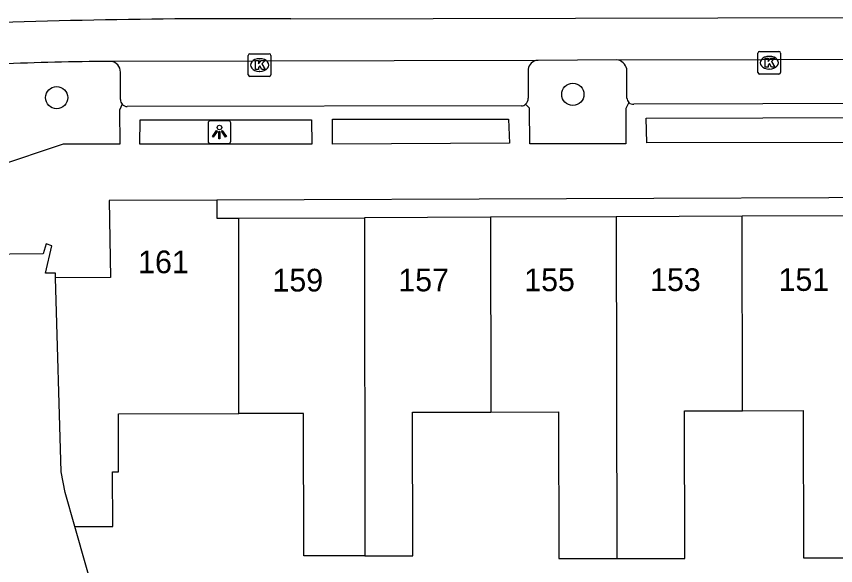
# Model space of a CAD drawing. Extents: x 159718 to 160783, y 383290 to 384030.
# Drawn here: x 160075.74 to 160111.85, y 383730.22 to 383754.43 of the extents above; entities that cross this region are included whole.
import ezdxf

# ---------------------------------------------------------------- set-up
doc = ezdxf.new("R2010")
doc.units = 0
for name, color, linetype in [('IMGEO_Boom', 7, 'Continuous'), ('IMGEO_Kolk', 7, 'Continuous'), ('IMGEO_Lichtpunt', 7, 'Continuous'), ('IMGEO_Pand', 7, 'Continuous'), ('IMGEO_Pand_nummerreeks', 7, 'Continuous'), ('IMGEO_Parkeervlak_open', 7, 'Continuous'), ('IMGEO_Rijbaan_lokaal_gesloten', 7, 'Continuous'), ('IMGEO_Voetpad_open', 7, 'Continuous')]:
    doc.layers.add(name, color=color, linetype=linetype)

msp = doc.modelspace()

# ---------------------------------------------------------------- linework, layer by layer
at = {"layer": 'IMGEO_Boom'}
for centre in [(160077.515, 383750.855), (160100.268, 383750.997)]:
    msp.add_circle(centre, 0.489, dxfattribs=at)
at = {"layer": 'IMGEO_Kolk'}
for p, q in [((160086.037, 383752.789), (160086.889, 383752.789)), ((160108.428, 383751.964), (160108.428, 383752.816)), ((160108.503, 383752.89), (160109.355, 383752.89)), ((160109.429, 383752.816), (160109.429, 383751.964)), ((160085.962, 383751.863), (160085.962, 383752.715)), ((160086.45, 383752.569), (160086.475, 383752.569)), ((160086.963, 383752.715), (160086.963, 383751.863)), ((160108.916, 383752.67), (160108.941, 383752.67)), ((160108.939, 383752.11), (160108.914, 383752.11)), ((160086.889, 383751.789), (160086.037, 383751.789)), ((160086.473, 383752.009), (160086.448, 383752.009)), ((160109.355, 383751.89), (160108.503, 383751.89))]:
    msp.add_line(p, q, dxfattribs=at)
for points in [[(160086.037, 383752.789), (160086.889, 383752.789)], [(160108.428, 383751.964), (160108.428, 383752.816)], [(160108.503, 383752.89), (160109.355, 383752.89)], [(160109.429, 383752.816), (160109.429, 383751.964)], [(160085.962, 383751.863), (160085.962, 383752.715)], [(160086.283, 383752.489), (160086.406, 383752.489), (160086.406, 383752.338), (160086.536, 383752.489), (160086.7, 383752.489), (160086.554, 383752.338), (160086.707, 383752.089), (160086.555, 383752.089), (160086.47, 383752.253), (160086.406, 383752.186), (160086.406, 383752.089), (160086.283, 383752.089), (160086.283, 383752.489)], [(160086.963, 383752.715), (160086.963, 383751.863)], [(160108.749, 383752.59), (160108.872, 383752.59), (160108.872, 383752.439), (160109.002, 383752.59), (160109.166, 383752.59), (160109.02, 383752.439), (160109.173, 383752.19), (160109.021, 383752.19), (160108.936, 383752.354), (160108.872, 383752.287), (160108.872, 383752.19), (160108.749, 383752.19), (160108.749, 383752.59)], [(160086.889, 383751.789), (160086.037, 383751.789)], [(160109.355, 383751.89), (160108.503, 383751.89)]]:
    msp.add_lwpolyline(points, dxfattribs=at)
for centre, start, end in [((160086.039, 383752.713), 91.552, 178.448), ((160086.039, 383752.713), 91.552, 178.448), ((160086.887, 383752.713), 1.552, 88.448), ((160086.887, 383752.713), 1.552, 88.448), ((160108.505, 383752.814), 91.552, 178.448), ((160108.505, 383752.814), 91.552, 178.448), ((160109.353, 383752.814), 1.552, 88.448), ((160109.353, 383752.814), 1.552, 88.448), ((160086.039, 383751.865), 181.552, 268.448), ((160086.039, 383751.865), 181.552, 268.448), ((160086.887, 383751.865), 271.552, 358.448), ((160086.887, 383751.865), 271.552, 358.448), ((160108.505, 383751.966), 181.552, 268.448), ((160108.505, 383751.966), 181.552, 268.448), ((160109.353, 383751.966), 271.552, 358.448), ((160109.353, 383751.966), 271.552, 358.448)]:
    msp.add_arc(centre, 0.0765, start, end, dxfattribs=at)
for centre, major_axis, ratio, start_param, end_param in [((160086.449, 383752.289), (-0.387, 0.002), 0.722429, 4.712389, 7.853982), ((160086.474, 383752.289), (-0.39, 0.002), 0.717154, 1.570796, 4.712389), ((160108.915, 383752.39), (-0.387, 0.002), 0.722429, 4.712389, 7.853982), ((160108.94, 383752.39), (-0.39, 0.002), 0.717154, 1.570796, 4.712389)]:
    msp.add_ellipse(centre, major_axis=major_axis, ratio=ratio, start_param=start_param, end_param=end_param, dxfattribs=at)
at = {"layer": 'IMGEO_Lichtpunt'}
for p, q in [((160084.192, 383749.737), (160084.192, 383748.93)), ((160084.192, 383749.737), (160084.192, 383748.93)), ((160085.094, 383749.832), (160084.286, 383749.832)), ((160085.094, 383749.832), (160084.286, 383749.832)), ((160085.188, 383748.93), (160085.188, 383749.737)), ((160085.188, 383748.93), (160085.188, 383749.737)), ((160084.286, 383748.836), (160085.094, 383748.836)), ((160084.286, 383748.836), (160085.094, 383748.836))]:
    msp.add_line(p, q, dxfattribs=at)
for points in [[(160084.566, 383749.401), (160084.605, 383749.373), (160084.417, 383749.111), (160084.379, 383749.138), (160084.566, 383749.401)], [(160084.668, 383749.353), (160084.715, 383749.353), (160084.715, 383749.031), (160084.668, 383749.031), (160084.668, 383749.353)], [(160084.778, 383749.373), (160084.816, 383749.4), (160085.003, 383749.138), (160084.964, 383749.11), (160084.778, 383749.373)]]:
    msp.add_lwpolyline(points, dxfattribs=at)
msp.add_circle((160084.691, 383749.535), 0.0994, dxfattribs=at)
for centre, start, end in [((160084.286, 383749.737), 90, 180), ((160084.286, 383749.737), 90, 180), ((160085.094, 383749.737), 0, 90), ((160085.094, 383749.737), 0, 90), ((160084.286, 383748.93), 180, 270), ((160084.286, 383748.93), 180, 270), ((160085.094, 383748.93), 270, 0), ((160085.094, 383748.93), 270, 360)]:
    msp.add_arc(centre, 0.0946, start, end, dxfattribs=at)
at = {"layer": 'IMGEO_Pand'}
for points in [[(160084.576, 383746.335), (160079.829, 383746.321), (160079.887, 383742.919), (160077.468, 383742.909)], [(160084.576, 383746.335), (160084.578, 383745.535), (160085.54, 383745.538)], [(160096.637, 383745.58), (160091.088, 383745.559)], [(160102.185, 383745.601), (160096.637, 383745.58)], [(160096.637, 383745.58), (160096.648, 383736.994)], [(160107.734, 383745.622), (160102.185, 383745.601)], [(160102.185, 383745.601), (160102.203, 383730.54)], [(160113.282, 383745.643), (160107.734, 383745.622)], [(160107.745, 383737.052), (160107.734, 383745.622)], [(160085.54, 383745.538), (160091.088, 383745.559)], [(160085.55, 383736.923), (160085.54, 383745.538)], [(160091.088, 383745.559), (160091.106, 383730.657)], [(160077.468, 383742.909), (160077.467, 383743.109), (160077.018, 383743.115), (160077.303, 383744.324), (160077.049, 383744.402), (160076.918, 383743.972), (160073.988, 383743.935), (160073.846, 383744.362), (160054.838, 383738.238)], [(160078.32, 383731.948), (160077.893, 383733.449), (160077.721, 383734.353), (160077.468, 383742.909)], [(160078.32, 383731.948), (160079.987, 383731.951), (160079.983, 383734.356), (160080.244, 383734.356), (160080.24, 383736.916), (160085.55, 383736.923)], [(160091.106, 383730.657), (160088.41, 383730.654), (160088.402, 383736.926), (160085.55, 383736.923)], [(160091.106, 383730.657), (160093.21, 383730.66), (160093.203, 383736.99), (160096.648, 383736.994)], [(160096.648, 383736.994), (160099.643, 383736.998), (160099.651, 383730.537), (160102.203, 383730.54)], [(160102.203, 383730.54), (160105.2, 383730.544), (160105.193, 383737.049), (160107.745, 383737.052)], [(160107.745, 383737.052), (160110.423, 383737.056), (160110.431, 383730.566), (160113.3, 383730.57)], [(160085.28, 383707.469), (160078.32, 383731.948)]]:
    msp.add_lwpolyline(points, dxfattribs=at)
at = {"layer": 'IMGEO_Parkeervlak_open'}
for points in [[(160080.335, 383750.767), (160080.325, 383751.981)], [(160098.294, 383752.029), (160098.293, 383750.837)], [(160102.648, 383750.835), (160102.656, 383752.041)]]:
    msp.add_lwpolyline(points, dxfattribs=at)
for centre, radius, start, end in [((160079.873, 383751.993), 0.452, 358.4197, 84.7705), ((160098.739, 383752.05), 0.446, 103.6333, 182.7078), ((160102.132, 383751.998), 0.525, 4.7243, 72.1967), ((160080.607, 383750.738), 0.273, 173.8828, 221.1683), ((160097.995, 383750.794), 0.302, 309.9185, 8.1467), ((160102.937, 383750.849), 0.289, 182.7071, 227.3898)]:
    msp.add_arc(centre, radius, start, end, dxfattribs=at)
at = {"layer": 'IMGEO_Rijbaan_lokaal_gesloten'}
for points in [[(160087.833, 383754.324), (160131.736, 383754.435), (160131.735, 383752.627)], [(160079.914, 383752.444), (160079.852, 383752.446)], [(160098.634, 383752.483), (160079.914, 383752.444)], [(160102.293, 383752.498), (160102.201, 383752.519), (160098.745, 383752.495), (160098.634, 383752.483)], [(160114.948, 383752.54), (160102.293, 383752.498)]]:
    msp.add_lwpolyline(points, dxfattribs=at)
for centre, radius, start, end in [((160085.551, 383434.587), 319.746, 89.59108, 92.51971), ((160080.326, 383628.642), 123.805, 90.21915, 92.45796)]:
    msp.add_arc(centre, radius, start, end, dxfattribs=at)
at = {"layer": 'IMGEO_Voetpad_open'}
for points in [[(160102.741, 383750.636), (160102.607, 383750.369), (160102.607, 383748.819), (160098.379, 383748.818), (160098.355, 383750.385), (160098.188, 383750.563)], [(160080.401, 383750.558), (160080.289, 383750.299), (160080.298, 383748.799), (160077.808, 383748.803), (160074.798, 383747.796), (160074.691, 383750.162), (160074.555, 383750.401)], [(160098.001, 383750.492), (160080.628, 383750.467)], [(160114.334, 383750.594), (160102.952, 383750.559)], [(160089.674, 383748.8), (160089.672, 383749.905), (160097.436, 383749.905), (160097.473, 383748.842), (160089.674, 383748.8)], [(160103.524, 383748.855), (160103.508, 383749.948), (160113.785, 383749.982), (160113.799, 383748.872), (160103.524, 383748.855)], [(160088.767, 383748.796), (160081.183, 383748.798), (160081.191, 383749.868), (160088.754, 383749.875), (160088.767, 383748.796)], [(160130.817, 383746.508), (160084.576, 383746.335)]]:
    msp.add_lwpolyline(points, dxfattribs=at)
for centre, radius, start, end in [((160102.938, 383750.847), 0.288, 227.0302, 272.8728), ((160080.604, 383750.735), 0.269, 221.0879, 275.2223), ((160097.998, 383750.783), 0.291, 270.6819, 310.8996)]:
    msp.add_arc(centre, radius, start, end, dxfattribs=at)

# ---------------------------------------------------------------- texts
at = {"layer": 'IMGEO_Pand_nummerreeks'}
for s, rotation, p in [('161', 0.0573, (160081.108, 383743.112)), ('159', 0.0688, (160087.03, 383742.306)), ('157', 0.0688, (160092.578, 383742.313)), ('155', 0.0688, (160098.127, 383742.32)), ('153', 0.0688, (160103.675, 383742.327)), ('151', 0.0688, (160109.338, 383742.333))]:
    msp.add_text(s, height=1, rotation=rotation, dxfattribs=at).set_placement(p)

doc.saveas('drawing.dxf')
